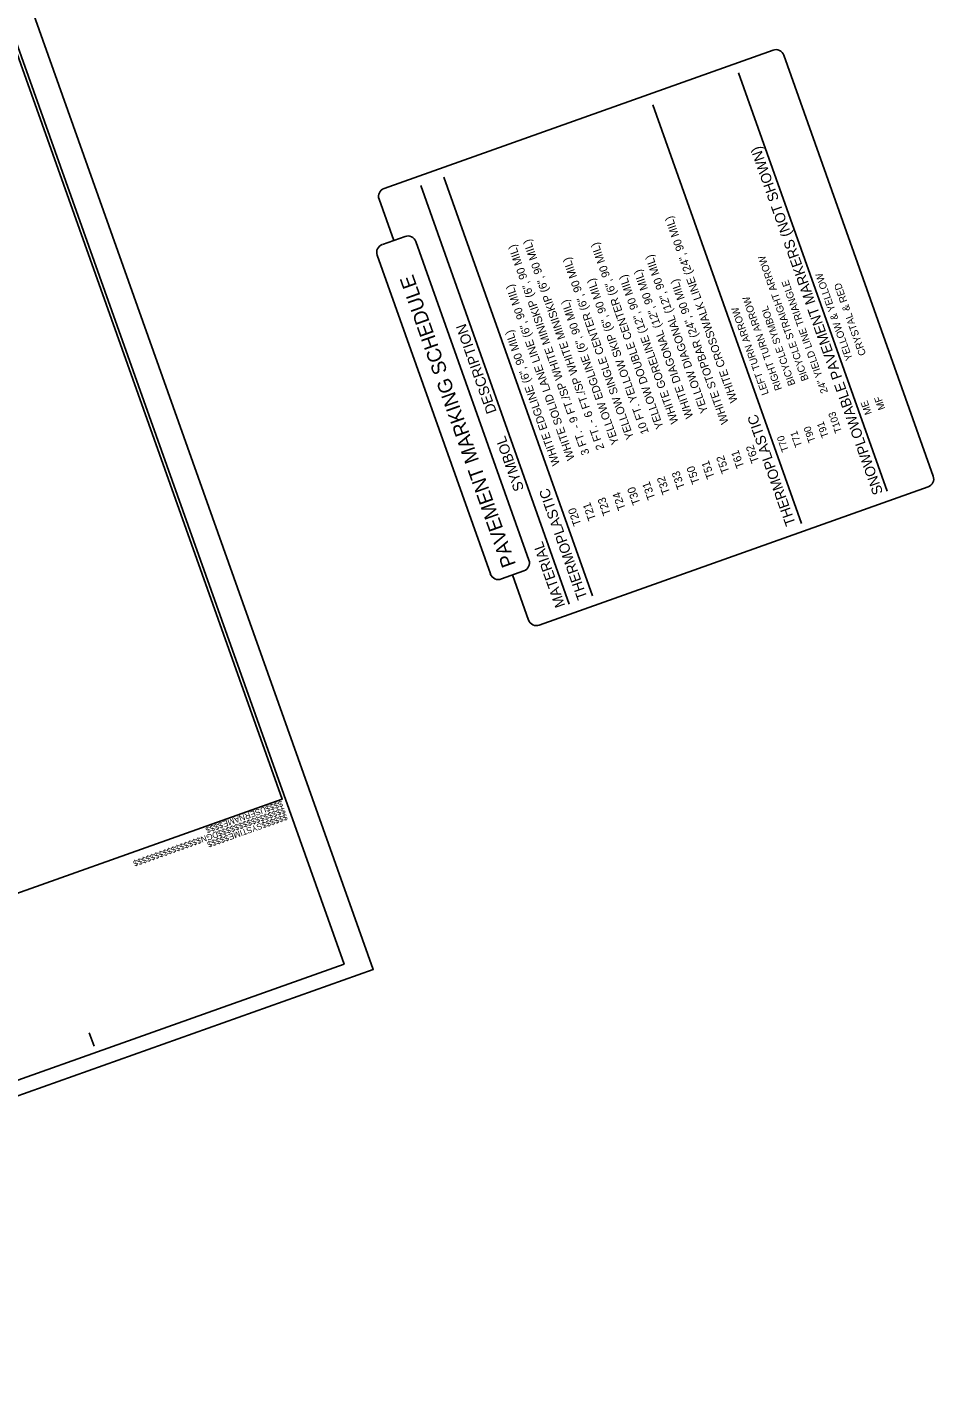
# Model space of a CAD drawing. Extents: x 1615843 to 1617934, y 901966 to 903921.
# Drawn here: x 1617141 to 1617934, y 901966 to 903158 of the extents above; entities that cross this region are included whole.
import ezdxf

# ---------------------------------------------------------------- set-up
doc = ezdxf.new("R2010")
doc.units = 0
for name, color, linetype in [('Sheet Block Revision CELL', 7, 'Continuous'), ('Sheet Border Standard 30in CELL', 7, 'Continuous'), ('Sheet Layout Plan Border', 7, 'Continuous'), ('Sheet North Arrow Point CELL', 7, 'Continuous'), ('Sheet Plot Border Inside CELL', 7, 'Continuous'), ('Sheet Plot Border Outside CELL', 7, 'Continuous')]:
    doc.layers.add(name, color=color, linetype=linetype)

msp = doc.modelspace()

# ---------------------------------------------------------------- linework, layer by layer
at = {"layer": 'Sheet Block Revision CELL'}
for p, q in [((1617892.9, 902752.4), (1617763, 903118.5)), ((1617818, 902724.3), (1617688.1, 903090.4)), ((1617635.3, 902660.9), (1617505.3, 903027.1)), ((1617615, 902653.7), (1617485.1, 903019.9))]:
    msp.add_line(p, q, dxfattribs=at)
at = {"layer": 'Sheet Border Standard 30in CELL'}
msp.add_line((1617199.5, 902267), (1617195.3, 902278.8), dxfattribs=at)
msp.add_lwpolyline([(1615872.3, 903544.7), (1616374.7, 902131.4), (1617364.1, 902483.1), (1616861.6, 903896.5)], close=True, dxfattribs=at)
at = {"layer": 'Sheet North Arrow Point CELL'}
for p, q in [((1617453.1, 903017.3), (1617793.2, 903138.3)), ((1617933.2, 902765.7), (1617802.6, 903133.9)), ((1617461.5, 902971.8), (1617448.7, 903007.9)), ((1617471.4, 902975.4), (1617451.6, 902968.3)), ((1617579.7, 902692.2), (1617480.8, 902970.9)), ((1617546, 902680.2), (1617447.1, 902958.9)), ((1617588.8, 902635.3), (1617928.8, 902756.3)), ((1617575.3, 902682.8), (1617555.8, 902675.8)), ((1617579.4, 902639.8), (1617565.4, 902679.2))]:
    msp.add_line(p, q, dxfattribs=at)
for centre, start, end in [((1617795.6, 903131.4), 19.5399, 109.5399), ((1617455.6, 903010.4), 109.5399, 199.5399), ((1617473.9, 902968.4), 19.57, 109.57), ((1617454, 902961.4), 109.5097, 199.57), ((1617926.3, 902763.2), 289.5399, 19.5399), ((1617572.8, 902689.7), 289.57, 19.57), ((1617552.9, 902682.6), 199.57, 292.6866), ((1617586.3, 902642.3), 199.5399, 289.5399)]:
    msp.add_arc(centre, 7.36, start, end, dxfattribs=at)
at = {"layer": 'Sheet Plot Border Inside CELL'}
msp.add_lwpolyline([(1615865.7, 903555.7), (1616423.9, 901985.4), (1617418.1, 902338.9), (1616859.8, 903909.1)], close=True, dxfattribs=at)
at = {"layer": 'Sheet Plot Border Outside CELL'}
msp.add_lwpolyline([(1615843, 903552.4), (1616407.1, 901965.7), (1617443.6, 902334.1), (1616879.5, 903920.8)], close=True, dxfattribs=at)

# ---------------------------------------------------------------- texts
at = {"layer": 'Sheet Block Revision CELL'}
for s, height, rotation, p in [('SNOWPLOWABLE PAVEMENT MARKERS (NOT SHOWN)', 9, 109.5305, (1617889.5, 902751.2)), ('WHITE CROSSWALK LINE (24", 90 MIL)', 7, 109.4731, (1617762.4, 902831.3)), ('3 FT. - 9 FT./SP WHITE MINISKIP (6", 90 MIL)', 7, 109.4731, (1617632.8, 902785.4)), ('2 FT. - 6 FT./SP WHITE MINISKIP (6", 90 MIL)', 7, 109.4731, (1617645.8, 902790)), ('YELLOW DOUBLE CENTER (6", 90 MIL)', 7, 109.4731, (1617697.6, 902808.3)), ('YELLOW SINGLE CENTER (6", 90 MIL)', 7, 109.4731, (1617671.7, 902799.2)), ('YELLOW DIAGONAL (12", 90 MIL)', 7, 109.4731, (1617736.5, 902822.1)), (' BICYCLE STRAIGHT ARROW', 6.3, 109.4997, (1617825.2, 902848)), ('10 FT. YELLOW SKIP (6", 90 MIL)', 7, 109.4731, (1617684.7, 902803.8)), ('WHITE GORELINE (12", 90 MIL)', 7, 109.4731, (1617710.6, 902812.9)), ('WHITE DIAGONAL (12", 90 MIL)', 7, 109.4731, (1617723.5, 902817.5)), ('     WHITE STOPBAR (24", 90 MIL)', 7, 109.4731, (1617758.8, 902800.3)), ('     24" YIELD LINE TRIANGLE', 6.3, 109.4997, (1617845.2, 902828.3)), ('YELLOW & YELLOW', 6.3, 109.5305, (1617862.9, 902868.1)), ('WHITE SOLID LANE LINE (6", 90 MIL)', 7, 109.4731, (1617619.9, 902780.9)), ('CRYSTAL & RED', 6.3, 109.5305, (1617874.6, 902872.3)), ('YELLOW EDGLINE (6", 90 MIL)', 7, 109.4731, (1617658.7, 902794.6)), (' RIGHT TURN ARROW', 6.3, 109.4997, (1617801.9, 902839.7)), (' BICYCLE SYMBOL', 6.3, 109.4997, (1617813.6, 902843.8)), (' LEFT TURN ARROW', 6.3, 109.4997, (1617790.3, 902835.6)), ('DESCRIPTION', 9, 109.4997, (1617551.6, 902822.2)), ('WHITE EDGLINE (6", 90 MIL)', 7, 109.4731, (1617606.9, 902776.3)), ('ME', 6.3, 109.5305, (1617879.7, 902820.6)), ('MF', 6.3, 109.5305, (1617891.4, 902824.8)), ('THERMOPLASTIC', 9, 109.4997, (1617813.1, 902724.1)), ('T103', 6.3, 109.4997, (1617853.6, 902804.6)), ('T90', 6.3, 109.4997, (1617830.4, 902796.3)), ('T91', 6.3, 109.4997, (1617842, 902800.4)), ('SYMBOL', 9, 109.4997, (1617575.6, 902754.3)), ('T70', 6.3, 109.4997, (1617807.1, 902788.1)), ('T71', 6.3, 109.4997, (1617818.8, 902792.2)), ('T52', 7, 109.4731, (1617755.2, 902769.3)), ('T61', 7, 109.4731, (1617768.1, 902773.9)), ('T62', 7, 109.4731, (1617781.1, 902778.5)), ('T50', 7, 109.4731, (1617729.3, 902760.1)), ('T51', 7, 109.4731, (1617742.2, 902764.7)), ('T31', 7, 109.4731, (1617690.4, 902746.4)), ('T32', 7, 109.4731, (1617703.3, 902751)), ('T33', 7, 109.4731, (1617716.3, 902755.6)), ('THERMOPLASTIC', 9, 109.4997, (1617631, 902659.4)), ('T23', 7, 109.4731, (1617651.5, 902732.6)), ('T24', 7, 109.4731, (1617664.5, 902737.2)), ('T30', 7, 109.4731, (1617677.4, 902741.8)), ('T20', 7, 109.4731, (1617625.6, 902723.5)), ('T21', 7, 109.4731, (1617638.5, 902728.1)), ('MATERIAL', 9, 109.4997, (1617611.6, 902652.5))]:
    msp.add_text(s, height=height, rotation=rotation, dxfattribs=at).set_placement(p)
at = {"layer": 'Sheet Border Standard 30in CELL'}
for s, p in [('$$$$$$$$$$$$$$$$DGN$$$$$$$$$$$$$$$$', (1617365.7, 902476.1)), ('$$$$USERNAME$$$$', (1617363.5, 902482)), ('$$$$$$SYSTIME$$$$$', (1617367.5, 902470.3))]:
    msp.add_text(s, height=5.25, rotation=199.5707, dxfattribs=at).set_placement(p)
at = {"layer": 'Sheet Layout Plan Border'}
msp.add_text('PAVEMENT MARKING SCHEDULE', height=12.479, rotation=109.5399, dxfattribs=at).set_placement((1617568.5, 902688.5))

doc.saveas('drawing.dxf')
